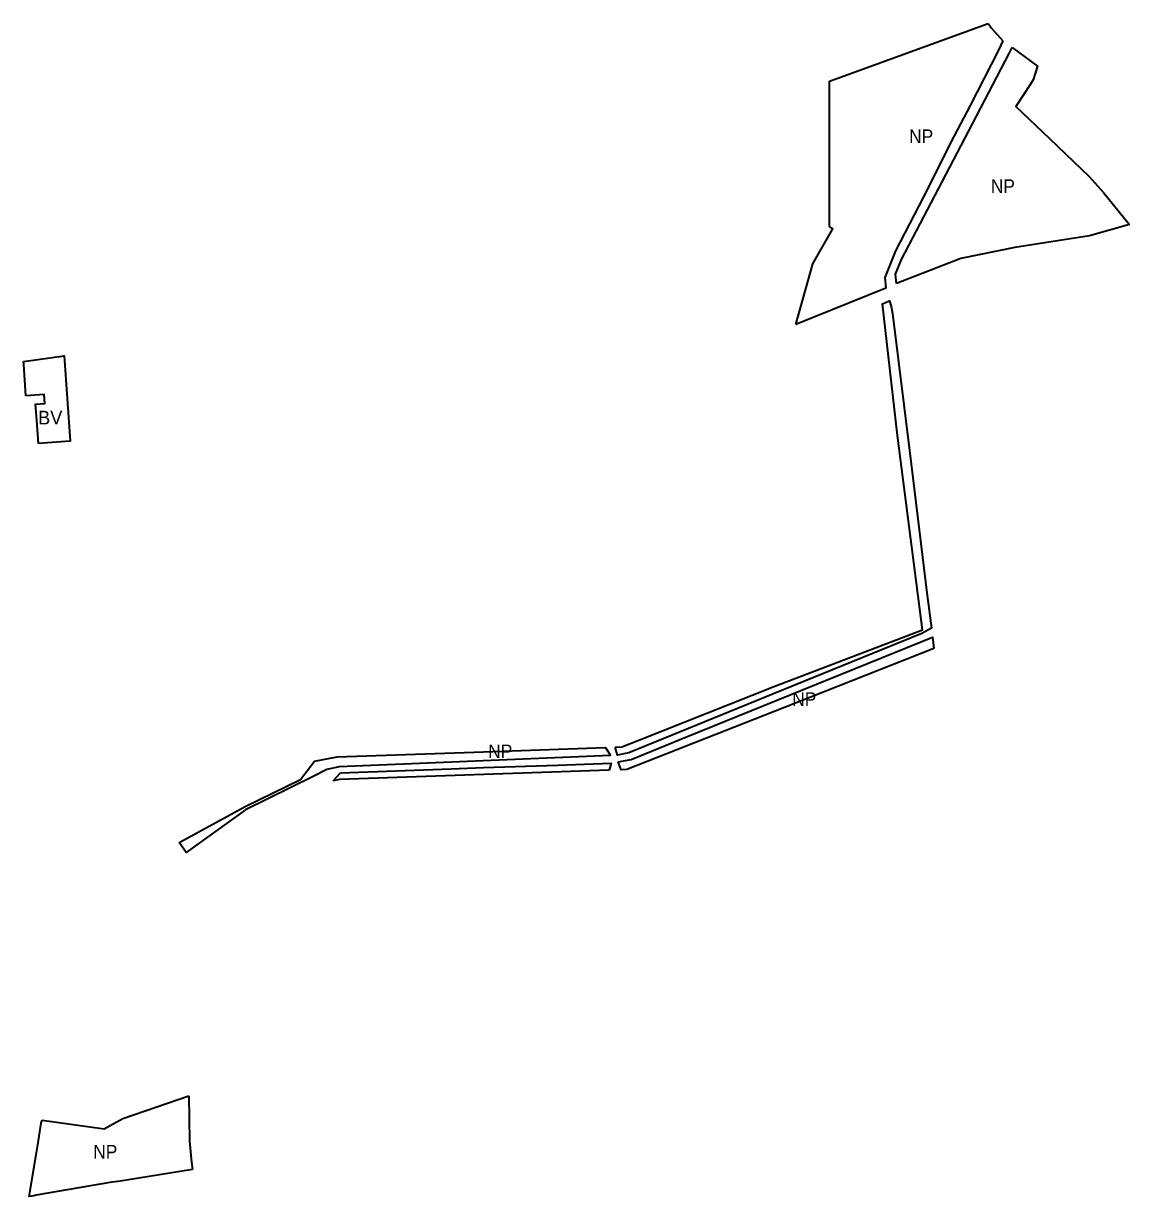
# Model space of a CAD drawing. Extents: x -650971 to -642489, y -1074311 to -1062745.
# Drawn here: x -643464 to -642489, y -1070593 to -1069560 of the extents above; entities that cross this region are included whole.
import ezdxf

# ---------------------------------------------------------------- set-up
doc = ezdxf.new("R2010")
doc.units = 0
doc.header["$LTSCALE"] = 4.8
for name, color, linetype, lineweight in [('3', 7, 'Continuous', 35), ('48', 7, 'Continuous', 35), ('62', 7, 'Continuous', 35)]:
    doc.layers.add(name, color=color, linetype=linetype, lineweight=lineweight)

msp = doc.modelspace()

# ---------------------------------------------------------------- linework, layer by layer
at = {"layer": '3'}
for points in [[(-643463.51, -1069857.44), (-643427.6, -1069852.59), (-643422.204, -1069927.68), (-643450.3, -1069929.7)], [(-643461.326, -1069887.84), (-643463.31, -1069860.18), (-643463.51, -1069857.44)], [(-643450.3, -1069929.7), (-643451.74, -1069909.63), (-643452.77, -1069895.25), (-643444.79, -1069894.68), (-643445.37, -1069886.7), (-643461.326, -1069887.84)]]:
    msp.add_lwpolyline(points, dxfattribs=at)
at = {"layer": '48'}
msp.add_line((-643190.42, -1070226.99), (-643184.22, -1070220.08), dxfattribs=at)
for points in [[(-642782.69, -1069824.93), (-642767.89, -1069771.42), (-642766.27, -1069769), (-642750.08, -1069740.57), (-642753.25, -1069738.59), (-642753.18, -1069610.65), (-642613.34, -1069559.68)], [(-642613.34, -1069559.68), (-642610.43, -1069563.79), (-642600.39, -1069574.87)], [(-642600.39, -1069574.87), (-642602.09, -1069578.86), (-642604.54, -1069583.67), (-642629.16, -1069631.94), (-642643.19, -1069658.58), (-642670.2, -1069712.37), (-642694.96, -1069760.17), (-642704.33, -1069783.54), (-642703.57, -1069792.88), (-642782.69, -1069824.93)], [(-642693.99, -1069788.85), (-642694.92, -1069780.68), (-642689.63, -1069767.81), (-642630.64, -1069654.82), (-642594.761, -1069586.091), (-642593.91, -1069584.46), (-642592.12, -1069580.95)], [(-642592.12, -1069580.95), (-642569.7, -1069597.42), (-642573.53, -1069609.34), (-642576.02, -1069613.14), (-642588.93, -1069632.86), (-642559.13, -1069661.18), (-642524.24, -1069694.66), (-642511.74, -1069708.63), (-642488.97, -1069736.54), (-642488.71, -1069736.85)], [(-642488.71, -1069736.85), (-642524.14, -1069746.8), (-642589.86, -1069757.1), (-642637.44, -1069766.81), (-642693.99, -1069788.85)], [(-642701.17, -1069804.49), (-642700.34, -1069804.12), (-642698.77, -1069809.17), (-642697.64, -1069815.14), (-642682.78, -1069935.98), (-642667.19, -1070063.71), (-642663.28, -1070092.67), (-642671.9, -1070097.32), (-642802.38, -1070150.51), (-642930.02, -1070202.54), (-642940.12, -1070204.42), (-642942.12, -1070197.4)], [(-642942.12, -1070197.4), (-642936.02, -1070197.23), (-642921.03, -1070191.32), (-642801.19, -1070143.75), (-642671.23, -1070094.16), (-642693.2, -1069922.89), (-642706.3, -1069806.69), (-642701.17, -1069804.49)], [(-642939.51, -1070210.35), (-642928.07, -1070208.21), (-642879.2, -1070188.43), (-642662.32, -1070100.64), (-642661.13, -1070110.48)], [(-642661.13, -1070110.48), (-642792.87, -1070162.36), (-642931.88, -1070217.1), (-642936.88, -1070217.27), (-642939.51, -1070210.35)], [(-643326.26, -1070281.43), (-643267.55, -1070249.49), (-643219.4, -1070225.8), (-643207.1, -1070209.72), (-643187.06, -1070205.98), (-643066.26, -1070201.69), (-642950.42, -1070197.58), (-642946.24, -1070204.83)], [(-642946.24, -1070204.83), (-643086.36, -1070210.57), (-643185.16, -1070214.62), (-643196.16, -1070217.22), (-643208.09, -1070223.14), (-643267.75, -1070252.77), (-643320, -1070290.2), (-643326.26, -1070281.43)], [(-642947.42, -1070217.64), (-643184.86, -1070225.91), (-643190.42, -1070226.99)], [(-643184.22, -1070220.08), (-643086.58, -1070216.57), (-643058.07, -1070215.38), (-642992.64, -1070213.18), (-642945.59, -1070211.49), (-642947.42, -1070217.64)], [(-643446.89, -1070526.01), (-643392.41, -1070533.68), (-643376.07, -1070524.59), (-643317.9, -1070504.73)], [(-643317.9, -1070504.73), (-643317.08, -1070544.75), (-643315.27, -1070563.2), (-643314.51, -1070569.69)], [(-643454.28, -1070592.709), (-643458.42, -1070593.43), (-643452.14, -1070554.77), (-643450.98, -1070547.74), (-643447.79, -1070528.63), (-643446.89, -1070526.01)], [(-643314.51, -1070569.69), (-643380.08, -1070580.09), (-643380.35, -1070580.14), (-643385.72, -1070580.86), (-643452.22, -1070592.35), (-643454.28, -1070592.709)]]:
    msp.add_lwpolyline(points, dxfattribs=at)

# ---------------------------------------------------------------- texts
at = {"layer": '62', "width": 0.95}
for p in [(-642682.928, -1069665.096), (-642610.928, -1069709.096), (-642785.928, -1070161.096), (-643053.928, -1070207.096), (-643401.985, -1070559.967)]:
    msp.add_text('NP', height=12, dxfattribs=at).set_placement(p)
at = {"layer": '62'}
msp.add_text('BV', height=12, dxfattribs=at).set_placement((-643450.639, -1069913.037))

doc.saveas('drawing.dxf')
